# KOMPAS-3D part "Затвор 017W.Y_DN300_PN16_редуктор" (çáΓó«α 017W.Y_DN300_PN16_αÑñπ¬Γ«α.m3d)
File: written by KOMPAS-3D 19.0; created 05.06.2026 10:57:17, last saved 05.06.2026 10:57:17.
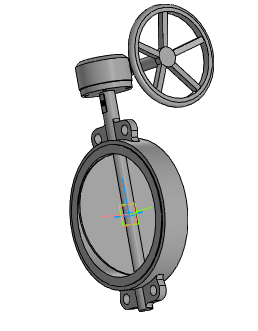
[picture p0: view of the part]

Document properties: Автор: Энергия; Полное имя файла: ..\..\..\3d для проектировщиков\x.x Тип 017W.Y(S) Затвор дисковый поворотный межфланцевый\Затвор 017W.Y(S)_DN50-DN1200_редуктор\Затвор 017W.Y_DN300_PN16_редуктор.a3d

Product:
- Part/product: Затвор 017W.Y_DN300_PN16_редуктор
    Масса: 39.4908

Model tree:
1. Операция без истории:1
